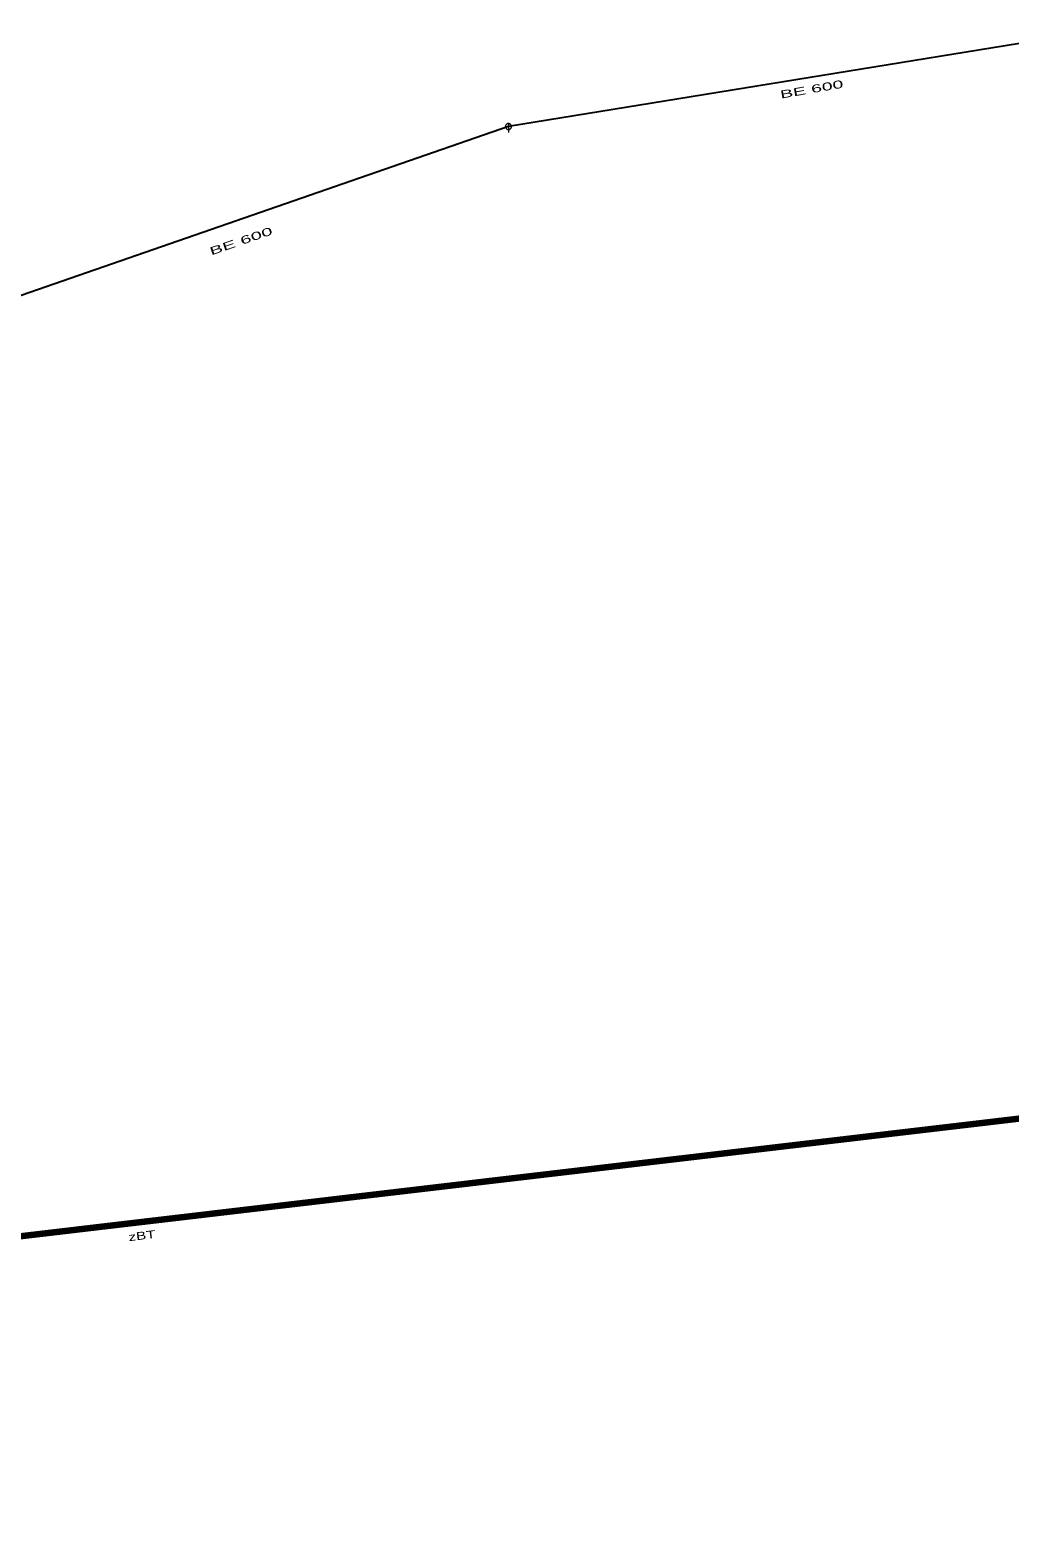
# Model space of a CAD drawing. Extents: x -687468 to -685917, y -974192 to -973456.
# Drawn here: x -686414.5 to -686331.6, y -974006.4 to -973878.9 of the extents above; entities that cross this region are included whole.
import ezdxf
from ezdxf.enums import TextEntityAlignment as Align

# ---------------------------------------------------------------- set-up
doc = ezdxf.new("R2010")
doc.units = 0
doc.header["$LTSCALE"] = 0.27
for name, color, linetype, lineweight in [('1', 7, 'Continuous', 13), ('14', 7, 'Continuous', 25), ('22', 7, 'Continuous', 13), ('27', 7, 'Continuous', 158)]:
    doc.layers.add(name, color=color, linetype=linetype, lineweight=lineweight)

msp = doc.modelspace()

# ---------------------------------------------------------------- linework, layer by layer
at = {"layer": '14'}
for p, q in [((-686323.946, -973878.859), (-686374.016, -973887.013)), ((-686374.016, -973887.013), (-686423.106, -973904.035)), ((-686200.654, -973955.608), (-686609.228, -974003.734))]:
    msp.add_line(p, q, dxfattribs=at)
at = {"layer": '22'}
msp.add_line((-686374.015, -973886.761), (-686374.016, -973887.505), dxfattribs=at)
msp.add_lwpolyline([(-686373.764, -973887.013), (-686373.765, -973886.987), (-686373.769, -973886.961), (-686373.775, -973886.935), (-686373.785, -973886.911), (-686373.797, -973886.887), (-686373.811, -973886.865), (-686373.828, -973886.844), (-686373.846, -973886.826), (-686373.867, -973886.809), (-686373.889, -973886.795), (-686373.913, -973886.783), (-686373.937, -973886.773), (-686373.963, -973886.767), (-686373.989, -973886.763), (-686374.015, -973886.761), (-686374.041, -973886.762), (-686374.067, -973886.766), (-686374.093, -973886.772), (-686374.118, -973886.782), (-686374.141, -973886.794), (-686374.163, -973886.808), (-686374.184, -973886.825), (-686374.202, -973886.843), (-686374.219, -973886.864), (-686374.233, -973886.886), (-686374.245, -973886.91), (-686374.255, -973886.934), (-686374.262, -973886.96), (-686374.266, -973886.986), (-686374.267, -973887.012), (-686374.267, -973887.038), (-686374.263, -973887.064), (-686374.256, -973887.09), (-686374.246, -973887.115), (-686374.234, -973887.138), (-686374.22, -973887.16), (-686374.203, -973887.181), (-686374.185, -973887.199), (-686374.164, -973887.216), (-686374.142, -973887.23), (-686374.119, -973887.242), (-686374.094, -973887.252), (-686374.068, -973887.259), (-686374.042, -973887.263), (-686374.016, -973887.265), (-686373.99, -973887.264), (-686373.964, -973887.26), (-686373.938, -973887.253), (-686373.914, -973887.243), (-686373.89, -973887.231), (-686373.868, -973887.217), (-686373.847, -973887.2), (-686373.829, -973887.182), (-686373.812, -973887.161), (-686373.798, -973887.139), (-686373.786, -973887.116), (-686373.776, -973887.091), (-686373.77, -973887.065), (-686373.766, -973887.039)], close=True, dxfattribs=at)
at = {"layer": '27'}
msp.add_lwpolyline([(-686200.654, -973955.608), (-686609.228, -974003.734), (-687014.163, -974137.428)], dxfattribs=at)
msp.add_lwpolyline([(-686200.654, -973955.608), (-686609.228, -974003.734), (-687014.163, -974137.428)], dxfattribs=at)

# ---------------------------------------------------------------- texts
at = {"layer": '1'}
for s, rotation, width, p in [('BE 600', 10, 1.85, (-686348.314, -973884.182)), ('BE 600', 19, 1.9, (-686396.53, -973897.013)), ('zBT ', 7, 1.45, (-686404.798, -973981.137))]:
    msp.add_text(s, height=0.6667, rotation=rotation, dxfattribs=dict(at, width=width)).set_placement(p, align=Align.CENTER)

doc.saveas('drawing.dxf')
